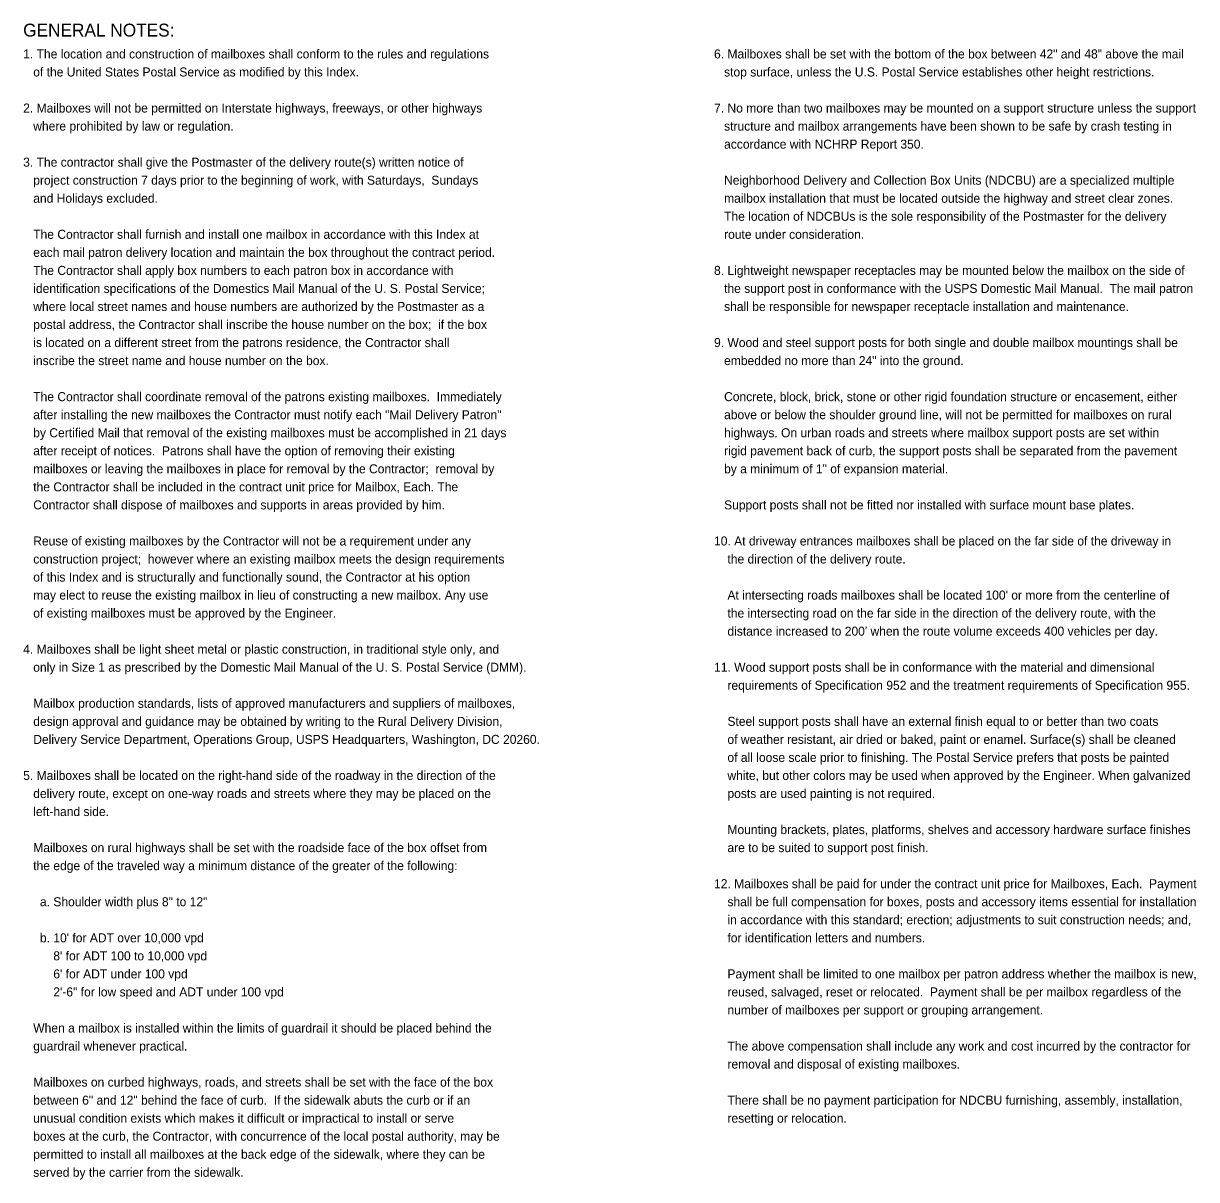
# Model space of a CAD drawing. Extents: x 0.28 to 9.39, y 0.64 to 9.61.
import ezdxf

# ---------------------------------------------------------------- set-up
doc = ezdxf.new("R2010")
doc.units = 0
doc.layers.add('Dimension', color=7, linetype='Continuous')

msp = doc.modelspace()

# ---------------------------------------------------------------- texts
at = {"layer": 'Dimension'}
for s, height, p in [('GENERAL NOTES:', 0.1, (0.2802, 9.5107)), ('1. The location and construction of mailboxes shall conform to the rules and regulations', 0.07, (0.2802, 9.3407)), ('6. Mailboxes shall be set with the bottom of the box between 42" and 48" above the mail ', 0.07, (5.6432, 9.3407)), ('   of the United States Postal Service as modified by this Index.', 0.07, (0.2802, 9.2007)), ('   stop surface, unless the U.S. Postal Service establishes other height restrictions.', 0.07, (5.6432, 9.2007)), ('2. Mailboxes will not be permitted on Interstate highways, freeways, or other highways ', 0.07, (0.2802, 8.9207)), ('7. No more than two mailboxes may be mounted on a support structure unless the support ', 0.07, (5.6432, 8.9207)), ('   where prohibited by law or regulation.', 0.07, (0.2802, 8.7807)), ('   structure and mailbox arrangements have been shown to be safe by crash testing in ', 0.07, (5.6432, 8.7807)), ('   accordance with NCHRP Report 350.', 0.07, (5.6432, 8.6407)), ('3. The contractor shall give the Postmaster of the delivery route(s) written notice of ', 0.07, (0.2802, 8.5007)), ('   project construction 7 days prior to the beginning of work, with Saturdays,  Sundays ', 0.07, (0.2802, 8.3607)), ('   Neighborhood Delivery and Collection Box Units (NDCBU) are a specialized multiple ', 0.07, (5.6432, 8.3607)), ('   and Holidays excluded.', 0.07, (0.2802, 8.2207)), ('   mailbox installation that must be located outside the highway and street clear zones. ', 0.07, (5.6432, 8.2207)), ('   The location of NDCBUs is the sole responsibility of the Postmaster for the delivery ', 0.07, (5.6432, 8.0807)), ('   The Contractor shall furnish and install one mailbox in accordance with this Index at ', 0.07, (0.2802, 7.9407)), ('   route under consideration.', 0.07, (5.6432, 7.9407)), ('   each mail patron delivery location and maintain the box throughout the contract period.', 0.07, (0.2802, 7.8007)), ('   The Contractor shall apply box numbers to each patron box in accordance with ', 0.07, (0.2802, 7.6607)), ('8. Lightweight newspaper receptacles may be mounted below the mailbox on the side of ', 0.07, (5.6432, 7.6607)), ('   identification specifications of the Domestics Mail Manual of the U. S. Postal Service; ', 0.07, (0.2802, 7.5207)), ('   the support post in conformance with the USPS Domestic Mail Manual.  The mail patron', 0.07, (5.6432, 7.5207)), ('   where local street names and house numbers are authorized by the Postmaster as a ', 0.07, (0.2802, 7.3807)), ('   shall be responsible for newspaper receptacle installation and maintenance.', 0.07, (5.6432, 7.3807)), ('   postal address, the Contractor shall inscribe the house number on the box;  if the box ', 0.07, (0.2802, 7.2407)), ('   is located on a different street from the patrons residence, the Contractor shall ', 0.07, (0.2802, 7.1007)), ('9. Wood and steel support posts for both single and double mailbox mountings shall be ', 0.07, (5.6432, 7.1007)), ('   inscribe the street name and house number on the box.', 0.07, (0.2802, 6.9607)), ('   embedded no more than 24" into the ground.', 0.07, (5.6432, 6.9607)), ('   The Contractor shall coordinate removal of the patrons existing mailboxes.  Immediately', 0.07, (0.2802, 6.6807)), ('   Concrete, block, brick, stone or other rigid foundation structure or encasement, either ', 0.07, (5.6432, 6.6807)), ('   after installing the new mailboxes the Contractor must notify each "Mail Delivery Patron"', 0.07, (0.2802, 6.5407)), ('   above or below the shoulder ground line, will not be permitted for mailboxes on rural ', 0.07, (5.6432, 6.5407)), ('   by Certified Mail that removal of the existing mailboxes must be accomplished in 21 days', 0.07, (0.2802, 6.4007)), ('   highways. On urban roads and streets where mailbox support posts are set within ', 0.07, (5.6432, 6.4007)), ('   after receipt of notices.  Patrons shall have the option of removing their existing ', 0.07, (0.2802, 6.2607)), ('   rigid pavement back of curb, the support posts shall be separated from the pavement ', 0.07, (5.6432, 6.2607)), ('   mailboxes or leaving the mailboxes in place for removal by the Contractor;  removal by ', 0.07, (0.2802, 6.1207)), ('   by a minimum of 1" of expansion material.', 0.07, (5.6432, 6.1207)), ('   the Contractor shall be included in the contract unit price for Mailbox, Each. The ', 0.07, (0.2802, 5.9807)), ('   Contractor shall dispose of mailboxes and supports in areas provided by him.', 0.07, (0.2802, 5.8407)), ('   Support posts shall not be fitted nor installed with surface mount base plates.', 0.07, (5.6432, 5.8407)), ('   Reuse of existing mailboxes by the Contractor will not be a requirement under any ', 0.07, (0.2802, 5.5607)), ('10. At driveway entrances mailboxes shall be placed on the far side of the driveway in ', 0.07, (5.6432, 5.5607)), ('   construction project;  however where an existing mailbox meets the design requirements', 0.07, (0.2802, 5.4207)), ('    the direction of the delivery route.', 0.07, (5.6432, 5.4207)), ('   of this Index and is structurally and functionally sound, the Contractor at his option ', 0.07, (0.2802, 5.2807)), ('   may elect to reuse the existing mailbox in lieu of constructing a new mailbox. Any use', 0.07, (0.2802, 5.1407)), ("    At intersecting roads mailboxes shall be located 100' or more from the centerline of ", 0.07, (5.6432, 5.1407)), ('   of existing mailboxes must be approved by the Engineer.', 0.07, (0.2802, 5.0007)), ('    the intersecting road on the far side in the direction of the delivery route, with the ', 0.07, (5.6432, 5.0007)), ("    distance increased to 200' when the route volume exceeds 400 vehicles per day.", 0.07, (5.6432, 4.8607)), ('4. Mailboxes shall be light sheet metal or plastic construction, in traditional style only, and', 0.07, (0.2802, 4.7207)), ('   only in Size 1 as prescribed by the Domestic Mail Manual of the U. S. Postal Service (DMM).', 0.07, (0.2802, 4.5807)), ('11. Wood support posts shall be in conformance with the material and dimensional ', 0.07, (5.6432, 4.5807)), ('    requirements of Specification 952 and the treatment requirements of Specification 955.', 0.07, (5.6432, 4.4407)), ('   Mailbox production standards, lists of approved manufacturers and suppliers of mailboxes,', 0.07, (0.2802, 4.3007)), ('   design approval and guidance may be obtained by writing to the Rural Delivery Division,  ', 0.07, (0.2802, 4.1607)), ('    Steel support posts shall have an external finish equal to or better than two coats ', 0.07, (5.6432, 4.1607)), ('   Delivery Service Department, Operations Group, USPS Headquarters, Washington, DC 20260. ', 0.07, (0.2802, 4.0207)), ('    of weather resistant, air dried or baked, paint or enamel. Surface(s) shall be cleaned ', 0.07, (5.6432, 4.0207)), ('    of all loose scale prior to finishing. The Postal Service prefers that posts be painted ', 0.07, (5.6432, 3.8807)), ('5. Mailboxes shall be located on the right-hand side of the roadway in the direction of the ', 0.07, (0.2802, 3.7407)), ('    white, but other colors may be used when approved by the Engineer. When galvanized ', 0.07, (5.6432, 3.7407)), ('   delivery route, except on one-way roads and streets where they may be placed on the ', 0.07, (0.2802, 3.6007)), ('    posts are used painting is not required.', 0.07, (5.6432, 3.6007)), ('   left-hand side.', 0.07, (0.2802, 3.4607)), ('    Mounting brackets, plates, platforms, shelves and accessory hardware surface finishes ', 0.07, (5.6432, 3.3207)), ('   Mailboxes on rural highways shall be set with the roadside face of the box offset from ', 0.07, (0.2802, 3.1807)), ('    are to be suited to support post finish.', 0.07, (5.6432, 3.1807)), ('   the edge of the traveled way a minimum distance of the greater of the following:', 0.07, (0.2802, 3.0407)), ('12. Mailboxes shall be paid for under the contract unit price for Mailboxes, Each.  Payment', 0.07, (5.6432, 2.9007)), ('     a. Shoulder width plus 8" to 12"', 0.07, (0.2802, 2.7607)), ('    shall be full compensation for boxes, posts and accessory items essential for installation', 0.07, (5.6432, 2.7607)), ('    in accordance with this standard; erection; adjustments to suit construction needs; and, ', 0.07, (5.6432, 2.6207)), ("     b. 10' for ADT over 10,000 vpd", 0.07, (0.2802, 2.4807)), ('    for identification letters and numbers.', 0.07, (5.6432, 2.4807)), ("         8' for ADT 100 to 10,000 vpd", 0.07, (0.2802, 2.3407)), ("         6' for ADT under 100 vpd", 0.07, (0.2802, 2.2007)), ('    Payment shall be limited to one mailbox per patron address whether the mailbox is new,', 0.07, (5.6432, 2.2007)), ('         2\'-6" for low speed and ADT under 100 vpd', 0.07, (0.2802, 2.0607)), ('    reused, salvaged, reset or relocated.  Payment shall be per mailbox regardless of the ', 0.07, (5.6432, 2.0607)), ('    number of mailboxes per support or grouping arrangement.', 0.07, (5.6432, 1.9207)), ('   When a mailbox is installed within the limits of guardrail it should be placed behind the ', 0.07, (0.2802, 1.7807)), ('   guardrail whenever practical.', 0.07, (0.2802, 1.6407)), ('    The above compensation shall include any work and cost incurred by the contractor for', 0.07, (5.6432, 1.6407)), ('    removal and disposal of existing mailboxes.', 0.07, (5.6432, 1.5007)), ('   Mailboxes on curbed highways, roads, and streets shall be set with the face of the box ', 0.07, (0.2802, 1.3607)), ('   between 6" and 12" behind the face of curb.  If the sidewalk abuts the curb or if an ', 0.07, (0.2802, 1.2207)), ('    There shall be no payment participation for NDCBU furnishing, assembly, installation, ', 0.07, (5.6432, 1.2207)), ('   unusual condition exists which makes it difficult or impractical to install or serve ', 0.07, (0.2802, 1.0807)), ('    resetting or relocation. ', 0.07, (5.6432, 1.0807)), ('   boxes at the curb, the Contractor, with concurrence of the local postal authority, may be ', 0.07, (0.2802, 0.9407)), ('   permitted to install all mailboxes at the back edge of the sidewalk, where they can be ', 0.07, (0.2802, 0.8007)), ('   served by the carrier from the sidewalk.', 0.07, (0.2802, 0.6607))]:
    msp.add_text(s, height=height, dxfattribs=at).set_placement(p)

doc.saveas('drawing.dxf')
